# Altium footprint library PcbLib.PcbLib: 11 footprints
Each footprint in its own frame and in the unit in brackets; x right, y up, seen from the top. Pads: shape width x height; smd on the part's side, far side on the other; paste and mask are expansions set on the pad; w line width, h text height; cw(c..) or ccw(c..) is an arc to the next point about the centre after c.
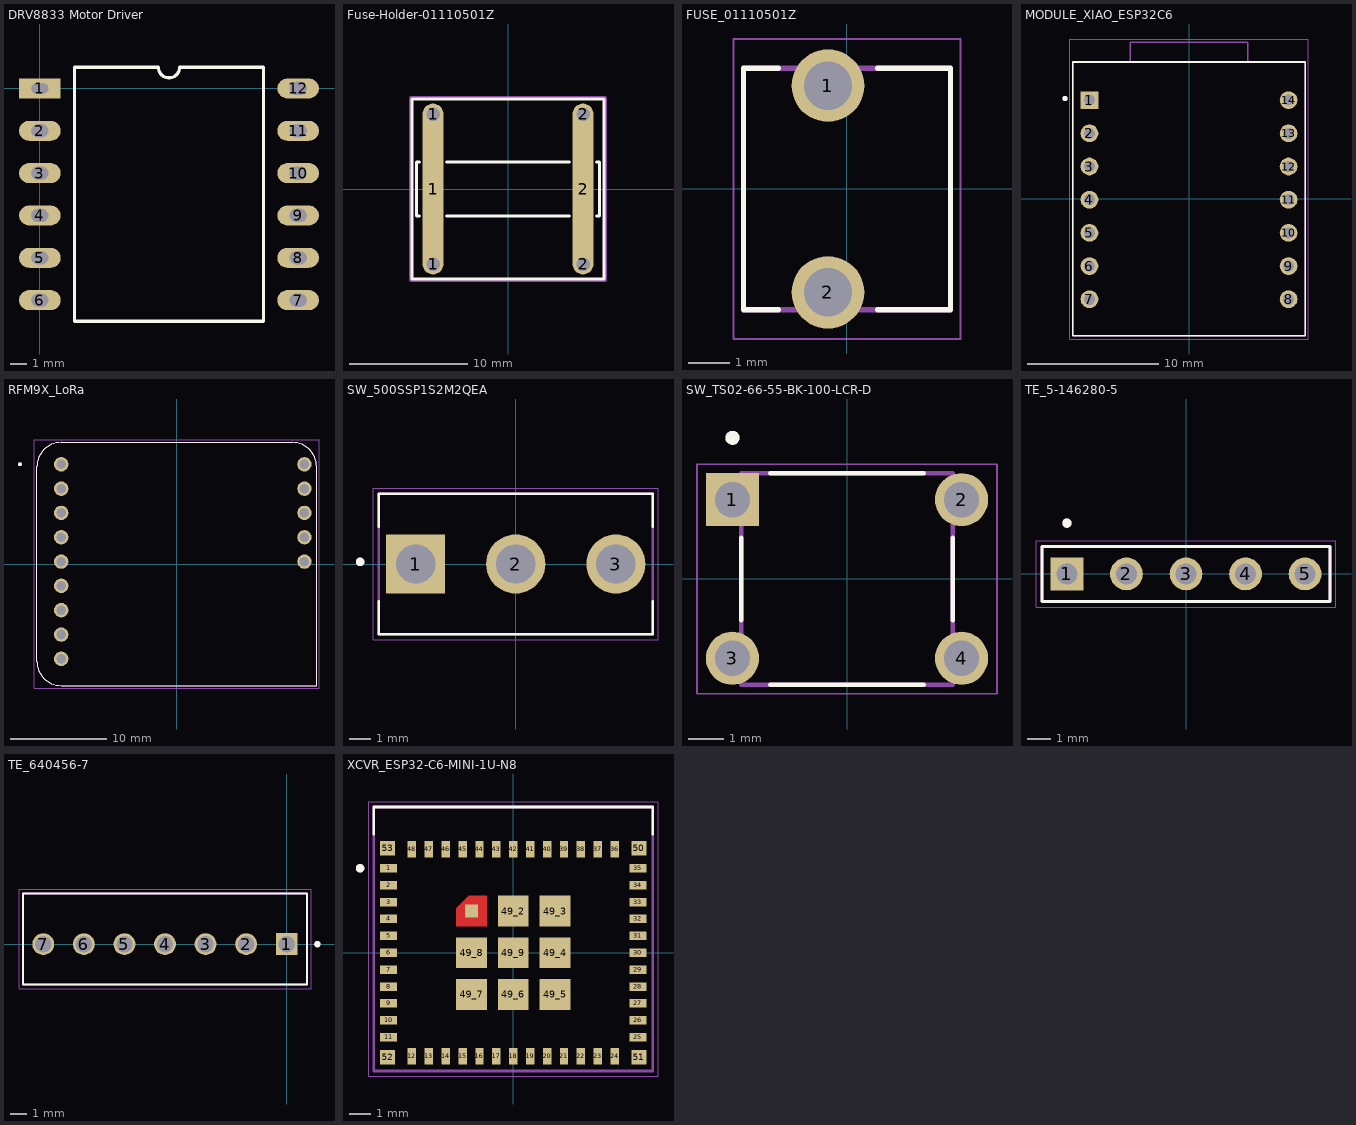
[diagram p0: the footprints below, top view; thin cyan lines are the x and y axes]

## DRV8833 Motor Driver [mm]
pads (12):
  rect 2.5x1.2 hole 0.6 slot 1.016 at 0 deg: 1(0,0)
  oval 2.5x1.2 hole 0.778 slot 1.016 at 0 deg: 2(0,-2.54) 3(0,-5.08) 4(0,-7.62) 5(0,-10.16) 6(0,-12.7) 7(15.5,-12.7) 8(15.5,-10.16) 9(15.5,-7.62) 10(15.5,-5.08) 11(15.5,-2.54) 12(15.5,0)
Top Overlay:
  lines w0.2: 2.085,-13.97 13.415,-13.97 13.415,1.27 8.385,1.27 cw(c7.75,1.27) 7.115,1.27 2.085,1.27 2.085,-13.97

## Fuse-Holder-01110501Z [mil]
pads (6):
  round 70 hole 45: 1(-250,-250) 1(-250,250) 2(250,-250) 2(250,250)
  rect 70x500 smd: 1(-250,0) 2(250,0)
Top Overlay:
  lines w10: -295,-90 -305,-90 -305,90 -295,90 ; -205,-90 205,-90 ; -205,90 205,90 ; 295,-90 305,-90 305,90 295,90 ; -320,-300 -320,300 320,300 320,-300 -320,-300
Mechanical 4:
  lines w10: -325,-305 -325,305 325,305 325,-305 -325,-305
Mechanical 6:
  text "'.Designator'" at -56.68,404.29 h39.37

## FUSE_01110501Z [mm]
height 7
pads (2):
  round 1.755 hole 1.17 mask+0.102: 1(-0.46,2.5) 2(-0.46,-2.5)
Top Overlay:
  lines w0.127: -1.657,-2.921 -2.5,-2.921 -2.5,2.921 -1.657,2.921 ; 0.737,-2.921 2.5,-2.921 2.5,2.921 0.737,2.921
Mechanical 13:
  lines w0.127: -2.5,-2.921 -2.5,2.921 2.5,2.921 2.5,-2.921 -2.5,-2.921
Mechanical 15:
  lines w0.05: -2.75,-3.628 -2.75,3.628 2.75,3.628 2.75,-3.628 -2.75,-3.628

## MODULE_XIAO_ESP32C6 [mm]
pads (14):
  rect 1.358x1.358 / inner round 1.358 / far side rect 1.358x1.358 hole 0.85 mask+0.102: 1(-7.62,7.556)
  round 1.358 hole 0.85 mask+0.102: 2(-7.62,5.016) 3(-7.62,2.476) 4(-7.62,-0.064) 5(-7.62,-2.603) 6(-7.62,-5.143) 7(-7.62,-7.683) 8(7.62,-7.683) 9(7.62,-5.143) 10(7.62,-2.603) 11(7.62,-0.064) 12(7.62,2.476) 13(7.62,5.016) 14(7.62,7.556)
Top Overlay:
  circle w0.2: c-9.5,7.683 r0.1
  lines w0.127: -8.89,-10.477 8.89,-10.477 8.89,10.477 -8.89,10.477 -8.89,-10.477
Mechanical 13:
  circle w0.2: c-9.5,7.683 r0.1
  lines w0.127: -4.5,10.477 -4.5,11.987 4.5,11.987 4.5,10.477 ; -4.5,10.477 4.5,10.477 ; -4.5,10.477 -8.89,10.477 -8.89,-10.477 8.89,-10.477 8.89,10.477 4.5,10.477
Mechanical 15:
  lines w0.05: -9.14,-10.727 9.14,-10.727 9.14,12.237 -9.14,12.237 -9.14,-10.727
3D body "step_temp.STEP": height 4.21, standoff 0, extent -8.89,-10.477 8.89,11.986

## RFM9X_LoRa [mm] "RFM9X_LoRa"
pads (14):
  round 1.508 hole 1: U3_1(-12.065,10.414) U3_2(-12.065,7.874) U3_3(-12.065,5.334) U3_4(-12.065,2.794) U3_5(-12.065,0.254) U3_6(-12.065,-2.286) U3_7(-12.065,-4.826) U3_8(-12.065,-7.366) U3_9(-12.065,-9.906) U3_10(13.335,10.414) U3_11(13.335,7.874) U3_12(13.335,5.334) U3_13(13.335,2.794) U3_14(13.335,0.254)
Top Overlay:
  circle w0.2: c-16.373,10.414 r0.1
  lines w0.127: -14.605,-10.16 ccw(c-12.065,-10.16) -12.065,-12.7 14.605,-12.7 14.605,10.16 ccw(c12.065,10.16) 12.065,12.7 -12.065,12.7 ccw(c-12.065,10.16) -14.605,10.16 -14.605,-10.16
Mechanical 13:
  circle w0.2: c-16.373,10.414 r0.1
  lines w0.127: -14.605,-10.16 ccw(c-12.065,-10.16) -12.065,-12.7 14.605,-12.7 14.605,10.16 ccw(c12.065,10.16) 12.065,12.7 -12.065,12.7 ccw(c-12.065,10.16) -14.605,10.16 -14.605,-10.16
Mechanical 15:
  lines w0.05: -14.855,-12.95 -14.855,12.95 14.855,12.95 14.855,-12.95 -14.855,-12.95
3D body "step_temp.STEP": height 3.37, standoff 0, extent -14.605,-12.7 14.605,12.7

## SW_500SSP1S2M2QEA [mm]
height 13.59
pads (3):
  rect 2.775x2.775 / inner round 2.775 / far side rect 2.775x2.775 hole 1.85 mask+0.102: 1(-4.7,0)
  round 2.775 hole 1.85 mask+0.102: 2(0,0) 3(4.7,0)
Top Overlay:
  circle w0.2: c-7.3,0.1 r0.1
  lines w0.127: -6.425,-1.75 -6.425,-3.3 6.425,-3.3 6.425,-1.75 ; -6.425,1.75 -6.425,3.3 6.425,3.3 6.425,1.75
Mechanical 13:
  circle w0.2: c-7.3,0.1 r0.1
  lines w0.127: -6.425,-3.3 -6.425,3.3 6.425,3.3 6.425,-3.3 -6.425,-3.3
Mechanical 15:
  lines w0.05: -6.675,-3.55 -6.675,3.55 6.675,3.55 6.675,-3.55 -6.675,-3.55

## SW_TS02-66-55-BK-100-LCR-D [mm]
pads (4):
  rect 1.508x1.508 / inner round 1.508 / far side rect 1.508x1.508 hole 1: 1(-3.25,2.25)
  round 1.508 hole 1: 2(3.25,2.25) 3(-3.25,-2.25) 4(3.25,-2.25)
Top Overlay:
  circle w0.2: c-3.25,4.004 r0.1
  lines w0.127: -3,-1.176 -3,1.176 ; -2.176,-3 2.176,-3 ; -2.176,3 2.176,3 ; 3,-1.176 3,1.176
Mechanical 13:
  circle w0.2: c-3.25,4.004 r0.1
  lines w0.127: -3,-3 -3,3 3,3 3,-3 -3,-3
Mechanical 15:
  lines w0.05: -4.254,-3.254 4.254,-3.254 4.254,3.254 -4.254,3.254 -4.254,-3.254
3D body "step_temp.STEP": height 5.5, standoff -3.5, extent -3.95,-3 3.95,3

## TE_5-146280-5 [mm]
pads (5):
  rect 1.398x1.398 / inner round 1.398 / far side rect 1.398x1.398 hole 0.89: 1(-5.08,0)
  round 1.398 hole 0.89: 2(-2.54,0) 3(0,0) 4(2.54,0) 5(5.08,0)
Top Overlay:
  circle w0.2: c-5.08,2.17 r0.1
  lines w0.127: -6.15,-1.17 6.15,-1.17 6.15,1.17 -6.15,1.17 -6.15,-1.17
Mechanical 13:
  circle w0.2: c-5.08,2.17 r0.1
  lines w0.127: -6.15,-1.17 6.15,-1.17 6.15,1.17 -6.15,1.17 -6.15,-1.17
Mechanical 15:
  lines w0.05: -6.4,-1.42 6.4,-1.42 6.4,1.42 -6.4,1.42 -6.4,-1.42
3D body "step_temp.STEP": height 5.33, standoff -5.84, extent -6.147,-1.168 6.147,1.168

## TE_640456-7 [mm]
pads (7):
  rect 1.37x1.37 / inner round 1.37 / far side rect 1.37x1.37 hole 1.02: 1(0,0)
  round 1.37 hole 1.02: 2(-2.54,0) 3(-5.08,0) 4(-7.62,0) 5(-10.16,0) 6(-12.7,0) 7(-15.24,0)
Top Overlay:
  circle w0.2: c1.92,0 r0.1
  lines w0.127: -16.51,-2.54 1.27,-2.54 1.27,3.18 -16.51,3.18 -16.51,-2.54
Mechanical 13:
  circle w0.2: c1.92,0 r0.1
  lines w0.127: -16.51,-2.54 -16.51,3.18 ; -16.51,-2.54 1.27,-2.54 ; -16.51,-2.54 -16.51,3.18 ; -16.51,3.18 1.27,3.18 ; -16.51,3.18 1.27,3.18 ; 1.27,-2.54 1.27,3.18 ; 1.27,-2.54 1.27,3.18
Mechanical 15:
  lines w0.05: -16.76,-2.79 1.52,-2.79 1.52,3.43 -16.76,3.43 -16.76,-2.79
3D body "step_temp.STEP": height 10.03, standoff -3.94, extent -16.51,-2.54 1.27,3.175

## XCVR_ESP32-C6-MINI-1U-N8 [mm]
height 2.55
pads (61):
  rect 0.8x0.4 smd: 1(-5.9,4) 2(-5.9,3.2) 3(-5.9,2.4) 4(-5.9,1.6) 5(-5.9,0.8) 6(-5.9,0) 7(-5.9,-0.8) 8(-5.9,-1.6) 9(-5.9,-2.4) 10(-5.9,-3.2) 11(-5.9,-4) 25(5.9,-4) 26(5.9,-3.2) 27(5.9,-2.4) 28(5.9,-1.6) 29(5.9,-0.8) 30(5.9,0) 31(5.9,0.8) 32(5.9,1.6) 33(5.9,2.4) 34(5.9,3.2) 35(5.9,4)
  rect 0.4x0.8 smd: 12(-4.8,-4.9) 13(-4,-4.9) 14(-3.2,-4.9) 15(-2.4,-4.9) 16(-1.6,-4.9) 17(-0.8,-4.9) 18(0,-4.9) 19(0.8,-4.9) 20(1.6,-4.9) 21(2.4,-4.9) 22(3.2,-4.9) 23(4,-4.9) 24(4.8,-4.9) 36(4.8,4.9) 37(4,4.9) 38(3.2,4.9) 39(2.4,4.9) 40(1.6,4.9) 41(0.8,4.9) 42(0,4.9) 43(-0.8,4.9) 44(-1.6,4.9) 45(-2.4,4.9) 46(-3.2,4.9) 47(-4,4.9) 48(-4.8,4.9)
  rect 0.6x0.6 smd paste-1 mask+0: 49_1(-1.975,1.975)
  rect 1.45x1.45 smd: 49_2(0,1.975) 49_3(1.975,1.975) 49_4(1.975,0) 49_5(1.975,-1.975) 49_6(0,-1.975) 49_7(-1.975,-1.975) 49_8(-1.975,0) 49_9(0,0)
  rect 0.7x0.7 smd: 50(5.95,4.95) 51(5.95,-4.95) 52(-5.95,-4.95) 53(-5.95,4.95)
Top Layer:
  region: -1.25,1.25 -2.7,1.25 -2.7,2.1 -2.1,2.7 -1.25,2.7
Top Overlay:
  circle w0.2: c-7.25,4 r0.1
  lines w0.127: -6.6,5.62 -6.6,6.9 6.6,6.9 6.6,5.62
Top Paste:
  region: -1.25,1.25 -2.7,1.25 -2.7,2.1 -2.1,2.7 -1.25,2.7
Top Solder:
  region: -1.15,1.15 -2.8,1.15 -2.8,2.14 -2.14,2.8 -1.15,2.8
Mechanical 13:
  circle w0.2: c-7.25,4 r0.1
  lines w0.127: -6.6,-5.6 -6.6,6.9 6.6,6.9 6.6,-5.6 -6.6,-5.6
Mechanical 15:
  lines w0.05: -6.85,-5.85 6.85,-5.85 6.85,7.15 -6.85,7.15 -6.85,-5.85
3D body "step_temp.STEP": height 2.55, standoff 0, extent -6.6,-6.25 6.6,6.25

## XIAO_ESP32_C6 [mm] "ESP32 on a board"
height 5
